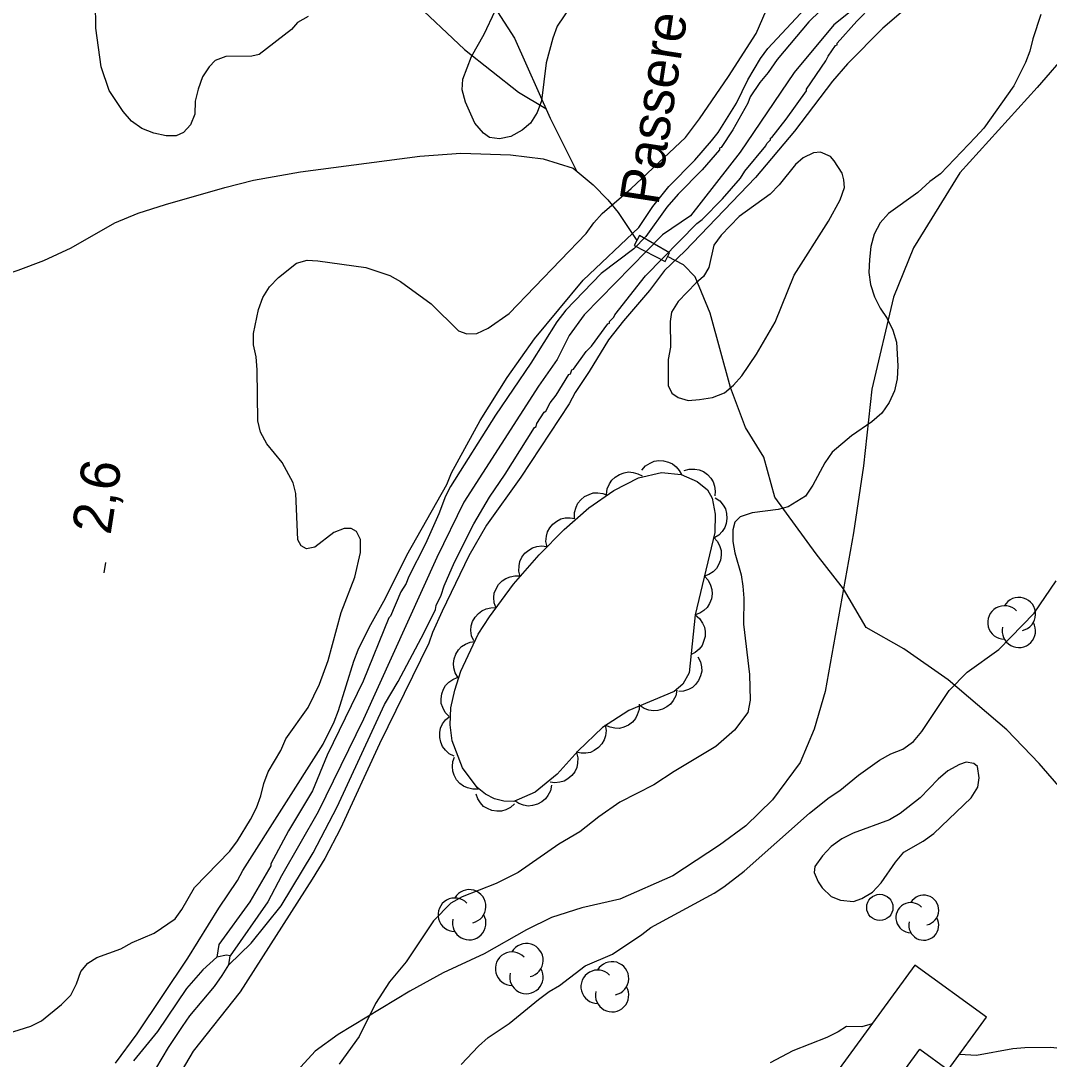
# Model space of a CAD drawing. Extents: x 282461 to 284471, y 5554090 to 5557646.
# Drawn here: x 283150.7 to 283229.1, y 5554690.7 to 5554769.8 of the extents above; entities that cross this region are included whole.
import ezdxf

# ---------------------------------------------------------------- set-up
doc = ezdxf.new("R2010")
doc.units = 0
for name, color, linetype in [('Niveau 2', 7, 'Continuous'), ('Niveau 22', 7, 'Continuous'), ('Niveau 26', 7, 'Continuous'), ('Niveau 3', 7, 'Continuous'), ('Niveau 31', 7, 'Continuous'), ('Niveau 36', 7, 'Continuous'), ('Niveau 4', 7, 'Continuous'), ('Niveau 44', 7, 'Continuous'), ('Niveau 7', 7, 'Continuous')]:
    doc.layers.add(name, color=color, linetype=linetype)

msp = doc.modelspace()

# ---------------------------------------------------------------- linework, layer by layer
at = {"layer": 'Niveau 2'}
for points in [[(283224.11, 5554775.88), (283216.37, 5554769.25), (283213.68, 5554766.53), (283212.54, 5554765.23), (283209.64, 5554761.41), (283206.67, 5554757.88), (283201.3, 5554752.27), (283199.75, 5554750.79), (283198.61, 5554749.27), (283196.62, 5554746.97), (283195.48, 5554745.5), (283194.01, 5554743.09), (283192.93, 5554741.51), (283192.48, 5554740.63), (283188.79, 5554735.05), (283186.18, 5554731.4), (283184.82, 5554729.06), (283182.8, 5554724.84), (283182.07, 5554723.21), (283181.79, 5554722.39), (283178.02, 5554714.72), (283175.05, 5554708.28), (283173.86, 5554706), (283172.9, 5554704.41), (283167.4, 5554695.85), (283163.82, 5554691.32), (283162.4, 5554688.91)], [(283172.58, 5554770.15), (283171.77, 5554769.68), (283171.32, 5554769.15), (283168.86, 5554767.25), (283168.28, 5554767.13), (283166.31, 5554767.09), (283165.5, 5554766.79), (283165.04, 5554766.32), (283164.53, 5554765.56), (283164.2, 5554764.62), (283163.98, 5554763.69), (283163.94, 5554762.71), (283163.61, 5554761.89), (283163.09, 5554761.3), (283162.52, 5554761.06), (283161.76, 5554761.05), (283160.83, 5554761.26), (283159.9, 5554761.6), (283159.13, 5554762.17), (283158.48, 5554762.91), (283157.41, 5554764.52), (283156.81, 5554766.3), (283156.41, 5554769.26), (283156.38, 5554771.23)], [(283157.91, 5554690.41), (283159.56, 5554692.64), (283163.41, 5554698.4), (283165.79, 5554702.21), (283167.21, 5554704.32), (283167.6, 5554705.09), (283173.72, 5554714.71), (283174.57, 5554716.41), (283174.9, 5554717.28), (283176.06, 5554721.02), (283176.4, 5554721.9), (283177.24, 5554723.59), (283178.48, 5554725.82), (283180.11, 5554729.1), (283183.16, 5554734.49), (283183.5, 5554735.37), (283185.7, 5554739.36), (283187.74, 5554742.64), (283189.84, 5554745.58), (283193.55, 5554750.06), (283197.78, 5554754.07), (283198.86, 5554755.66), (283200.06, 5554757.19), (283202.06, 5554759.2), (283203.31, 5554760.67), (283203.83, 5554761.32), (283205.24, 5554763.55), (283206.09, 5554765.31), (283207.05, 5554766.95), (283207.62, 5554767.71), (283210.82, 5554771.13)], [(283192.69, 5554771.07), (283191.56, 5554769.42), (283191.22, 5554768.49), (283190.73, 5554766.62), (283190.37, 5554763.71), (283190.04, 5554762.84), (283189.53, 5554762.02), (283188.9, 5554761.48), (283188.03, 5554761.01), (283187.17, 5554760.82), (283186.41, 5554760.92), (283185.94, 5554761.26), (283185.29, 5554762.01), (283184.57, 5554763.62), (283184.32, 5554764.55), (283184.36, 5554765.36), (283185.03, 5554767.11), (283185.99, 5554768.81), (283186.83, 5554770.57)], [(283194.98, 5554755.14), (283197.21, 5554757.03), (283201.33, 5554760.93), (283202.41, 5554762.34), (283204.62, 5554765.57), (283206.72, 5554768.85), (283207.5, 5554770.61)], [(283228.41, 5554770.31), (283227.81, 5554768.44), (283227.59, 5554767.5), (283227.25, 5554766.63), (283226.35, 5554764.87), (283224.08, 5554761.64), (283223.45, 5554760.94), (283220.77, 5554758.16), (283219.97, 5554757.57), (283219.05, 5554756.74), (283216.81, 5554755.14), (283216.18, 5554754.43), (283215.73, 5554753.55), (283215.46, 5554752.62), (283215.36, 5554751.63), (283215.31, 5554750.64), (283215.45, 5554749.72), (283215.75, 5554748.79), (283216.17, 5554747.93), (283216.71, 5554747.13), (283217.13, 5554746.26), (283217.43, 5554745.34), (283217.52, 5554743.54), (283217.48, 5554742.55), (283217.26, 5554741.62), (283216.87, 5554740.74), (283216.3, 5554739.92), (283215.55, 5554739.27), (283214, 5554738.2)], [(283212.68, 5554759.14), (283212.39, 5554759.48), (283211.63, 5554759.82), (283211.1, 5554759.75), (283210.3, 5554759.39), (283209.72, 5554758.86), (283208.47, 5554757.33), (283207.79, 5554756.62), (283205.43, 5554754.9), (283204.06, 5554753.48), (283203.49, 5554752.72), (283203.11, 5554751.03), (283202.72, 5554750.33), (283202.15, 5554749.85), (283200.78, 5554748.44), (283200.27, 5554747.62), (283200.16, 5554746.92), (283200.19, 5554744.95), (283200.03, 5554744.01), (283200.01, 5554742.04), (283200.31, 5554741.46), (283200.78, 5554741.12), (283201.54, 5554740.9), (283202.41, 5554740.97), (283203.39, 5554741.11), (283204.31, 5554741.47), (283205, 5554742.06), (283205.63, 5554742.77), (283206.76, 5554744.41), (283208.17, 5554746.87), (283209.63, 5554750.44), (283212.23, 5554754.54), (283213.14, 5554756.18), (283213.47, 5554757.12), (283213.4, 5554757.7), (283213.28, 5554758.22), (283212.68, 5554759.14)], [(283149.66, 5554692.66), (283151.45, 5554693.21), (283152.26, 5554693.63), (283153.8, 5554694.87), (283154.49, 5554695.58), (283154.94, 5554696.45), (283155.27, 5554697.39), (283155.79, 5554698.03), (283156.47, 5554698.45), (283158.32, 5554699.12), (283159.18, 5554699.6), (283160.86, 5554700.32), (283162.46, 5554701.39), (283162.97, 5554702.1), (283163.93, 5554703.79), (283166.62, 5554706.56), (283167.19, 5554707.33), (283168.2, 5554708.97), (283168.65, 5554709.85), (283168.99, 5554710.78), (283169.2, 5554711.71), (283169.54, 5554712.59), (283170.5, 5554714.23), (283170.89, 5554715.11), (283172.59, 5554717.51), (283173.44, 5554719.27), (283174.1, 5554721.08), (283175.09, 5554724.75), (283176.15, 5554727.44), (283176.58, 5554729.3), (283176.57, 5554730.29), (283176.27, 5554730.92), (283175.86, 5554731.15), (283175.34, 5554731.14), (283174.53, 5554730.84), (283173.09, 5554729.71), (283172.46, 5554729.58), (283172.05, 5554729.81), (283171.81, 5554730.27), (283171.64, 5554733.81), (283171.45, 5554734.62), (283170.61, 5554736.17), (283169.43, 5554737.6), (283168.95, 5554738.47), (283168.76, 5554739.33), (283168.7, 5554743.22), (283168.62, 5554744.21), (283168.43, 5554745.13), (283168.42, 5554746), (283168.8, 5554747.81), (283169.13, 5554748.74), (283169.64, 5554749.56), (283170.33, 5554750.27), (283171.7, 5554751.34), (283172.51, 5554751.58), (283173.32, 5554751.54), (283176.99, 5554751.02), (283178.8, 5554750.41), (283179.62, 5554749.96), (283181.97, 5554748.25), (283184.03, 5554746.2), (283184.68, 5554745.97), (283185.43, 5554745.99), (283186.29, 5554746.41), (283187.9, 5554747.53), (283193.78, 5554753.61), (283194.35, 5554754.43), (283194.98, 5554755.14)], [(283214, 5554738.2), (283212.51, 5554736.96), (283211.95, 5554736.13), (283211.05, 5554734.44), (283210.48, 5554733.61), (283209.16, 5554732.78), (283208.4, 5554732.59), (283206.43, 5554732.33), (283205.51, 5554732.03), (283205.11, 5554731.61), (283204.95, 5554731.03), (283204.96, 5554730.16), (283205.09, 5554729.29), (283205.58, 5554727.62), (283205.71, 5554726.75), (283205.78, 5554725.82), (283205.76, 5554723.85), (283206.22, 5554720.02), (283206.26, 5554718.05), (283206.1, 5554717.12), (283205.07, 5554715.77), (283203.64, 5554714.52), (283200.48, 5554712.62), (283198.93, 5554711.6), (283196.34, 5554710.29), (283194.73, 5554709.16), (283193.3, 5554708.03), (283191.69, 5554707.08), (283188.59, 5554704.94), (283186.92, 5554704.1), (283184.32, 5554703.07), (283183.46, 5554702.59), (283182.14, 5554701.24), (283180.05, 5554698.13), (283178.79, 5554696.6), (283177.72, 5554694.96), (283176.48, 5554692.44), (283174.95, 5554690.33)], [(283184.25, 5554690.3), (283185.56, 5554691.71), (283186.3, 5554692.36), (283187.91, 5554693.43), (283190.14, 5554695.26), (283190.94, 5554695.86), (283191.75, 5554696.33), (283193.7, 5554697.81), (283195.77, 5554698.72), (283198.01, 5554700.2), (283198.7, 5554700.74), (283203.53, 5554703.36), (283204.27, 5554703.84), (283205.82, 5554705.02), (283210.8, 5554709.45), (283212.29, 5554710.64), (283213.09, 5554711.17), (283214.52, 5554712.35), (283216.13, 5554713.48), (283216.99, 5554713.96), (283217.91, 5554714.32), (283218.72, 5554714.92), (283219.34, 5554715.68), (283221.44, 5554718.79), (283222.81, 5554720.2), (283225.22, 5554721.92), (283227.9, 5554724.69), (283229.6, 5554727.15)], [(283211.45, 5554704.23), (283211.75, 5554703.77), (283212.45, 5554703.09), (283213.15, 5554702.81), (283214.14, 5554702.71), (283214.78, 5554702.95), (283215.58, 5554703.43), (283216.26, 5554704.13), (283217.34, 5554705.71), (283217.97, 5554706.48), (283219.46, 5554707.31), (283220.26, 5554707.91), (283223.12, 5554710.62), (283223.62, 5554711.44), (283223.73, 5554712.13), (283223.6, 5554713), (283223.31, 5554713.23), (283222.73, 5554713.33), (283222.21, 5554713.15), (283221.34, 5554712.67), (283220.6, 5554712.03), (283219.23, 5554710.61), (283217.69, 5554709.43), (283216.88, 5554708.95), (283214.12, 5554707.92), (283213.25, 5554707.5), (283212.45, 5554706.91), (283211.77, 5554706.21), (283211.2, 5554705.39), (283211.15, 5554704.92), (283211.45, 5554704.23)], [(283215.56, 5554693.4), (283214.77, 5554693.16), (283213.61, 5554693.2), (283212.98, 5554692.78), (283212.11, 5554692.36), (283209.52, 5554691.34), (283207.79, 5554690.44)], [(283243.83, 5554692.72), (283243.61, 5554693.09), (283243.02, 5554693.55), (283242.32, 5554693.77), (283241.34, 5554693.64), (283239.55, 5554693.09), (283235.72, 5554692.62), (283234.86, 5554692.38), (283233.93, 5554692.25), (283231.45, 5554691.34), (283229.18, 5554691.59), (283227.21, 5554691.56), (283226.28, 5554691.49), (283223.51, 5554690.98), (283222.21, 5554691.07)]]:
    msp.add_lwpolyline(points, dxfattribs=at)
at = {"layer": 'Niveau 22'}
for points in [[(283179.89, 5554785.04), (283181.29, 5554780.85), (283182.12, 5554778.9), (283183.68, 5554775.68), (283184.87, 5554773.44), (283187.01, 5554770.51), (283188.32, 5554768.5), (283191.03, 5554762.39), (283193.07, 5554758.34)], [(283144.4, 5554779.69), (283145.96, 5554779.36), (283149.86, 5554778.84), (283154.29, 5554777.93), (283156.21, 5554777.72), (283157.78, 5554777.92), (283159.7, 5554777.83), (283161.67, 5554777.92), (283163.35, 5554777.89), (283164.93, 5554777.57), (283166.1, 5554777.06), (283166.92, 5554776.5), (283168.08, 5554776.05), (283170.53, 5554775.57), (283172.1, 5554775.36), (283173.67, 5554774.98), (283176, 5554774.21), (283178.16, 5554773.14), (283179.03, 5554772.58), (283180.5, 5554771.39), (283184.5, 5554767.62), (283188.62, 5554764.38), (283190.69, 5554763.13)], [(283230.61, 5554767.59), (283228.14, 5554764.73), (283222.24, 5554758.24), (283218.71, 5554752.53), (283217.19, 5554748.75), (283215.53, 5554741.75), (283214.91, 5554735.92), (283214.15, 5554730.81), (283211.98, 5554718.71), (283211.14, 5554715.86), (283210.07, 5554713.3), (283207.96, 5554710.47), (283205.95, 5554708.49), (283203.94, 5554707.02), (283200.37, 5554704.68), (283196.33, 5554702.91), (283193.44, 5554702.24), (283191.12, 5554701.5), (283189.22, 5554700.56), (283185.99, 5554698.73), (283182.87, 5554697.29), (283180.34, 5554695.88), (283174.86, 5554692.58), (283173.13, 5554691.33), (283166.57, 5554684.15)], [(283129.54, 5554744.82), (283131.68, 5554745.83), (283133.64, 5554746.62), (283141.55, 5554748.83), (283146.11, 5554749.49), (283147.73, 5554749.92), (283150.49, 5554750.83), (283152.45, 5554751.56), (283154.53, 5554752.52), (283157.86, 5554754.43), (283159.64, 5554755.15), (283161.72, 5554755.83), (283166.23, 5554757.12), (283168.42, 5554757.67), (283172.01, 5554758.31), (283181.09, 5554759.5), (283184.22, 5554759.73), (283188, 5554759.61), (283190.5, 5554759.3), (283192.78, 5554758.59), (283194.3, 5554757.33), (283195.43, 5554756.19), (283196.2, 5554755.21), (283197.64, 5554753.07)], [(283250.95, 5554693.69), (283248.15, 5554695.09), (283244.75, 5554697.58), (283235.92, 5554705.22), (283231.62, 5554709.39), (283228.3, 5554713.23), (283225.83, 5554715.8), (283221.37, 5554719.6), (283217.97, 5554721.97), (283215.11, 5554723.6), (283213.39, 5554726.53), (283211.3, 5554729.22), (283208.16, 5554733.52), (283207.3, 5554736.58), (283205.92, 5554738.82), (283204.77, 5554741.88), (283203.23, 5554747.55), (283202.08, 5554750.31), (283201.2, 5554751.23), (283199.97, 5554751.85)]]:
    msp.add_lwpolyline(points, dxfattribs=at)
at = {"layer": 'Niveau 26'}
msp.add_lwpolyline([(283197.84, 5554753.45), (283197.44, 5554752.69), (283199.79, 5554751.48), (283200.12, 5554752.15), (283197.84, 5554753.45)], dxfattribs=at)
at = {"layer": 'Niveau 3'}
msp.add_line((283157.04, 5554727.75), (283157.16, 5554728.54), dxfattribs=at)
at = {"layer": 'Niveau 31'}
msp.add_lwpolyline([(283213.13, 5554683.14), (283219.21, 5554691.46), (283221.35, 5554689.9), (283224.27, 5554693.9), (283218.82, 5554697.87), (283209.82, 5554685.56), (283213.13, 5554683.14)], dxfattribs=at)
at = {"layer": 'Niveau 36'}
msp.add_circle((283216.149, 5554702.268), 1, dxfattribs=at)
at = {"layer": 'Niveau 4'}
for points in [[(283216.27, 5554772.44), (283212.65, 5554769.51), (283209.61, 5554765.88), (283205.5, 5554759.81), (283201.73, 5554754.96), (283199.59, 5554753.5), (283193.62, 5554747.41), (283192.48, 5554745.83), (283191.57, 5554744.02), (283190.15, 5554741.98), (283184.44, 5554733.14), (283182.4, 5554728.94), (283176.8, 5554716.6), (283173.34, 5554709.55), (283170.55, 5554704.68), (283169.52, 5554702.7), (283166.65, 5554698.59)], [(283160.97, 5554689.96), (283161.93, 5554691.6), (283163.01, 5554693.19), (283163.58, 5554694.01), (283165.46, 5554696.25), (283166.03, 5554697.07), (283166.54, 5554697.89), (283166.65, 5554698.59), (283166.35, 5554698.64), (283165.63, 5554698.49), (283164.57, 5554697.51), (283163.31, 5554696.1), (283161.1, 5554692.81), (283159.28, 5554690.57)]]:
    msp.add_lwpolyline(points, dxfattribs=at)
at = {"layer": 'Niveau 44'}
for points in [[(283198.02, 5554735.58), (283198.3, 5554735.9), (283198.64, 5554736.12), (283198.95, 5554736.26), (283199.3, 5554736.31), (283199.67, 5554736.3), (283200.04, 5554736.2), (283200.35, 5554736.07), (283200.62, 5554735.84), (283200.87, 5554735.56), (283201.04, 5554735.24)], [(283202.09, 5554724.55), (283201.62, 5554720.14), (283201.15, 5554719.28), (283200.48, 5554718.73), (283197.03, 5554717.26), (283195.02, 5554715.98), (283193.15, 5554714.21), (283191.56, 5554712.41), (283189.88, 5554711.04), (283188.25, 5554710.34), (283187.49, 5554710.36), (283186.78, 5554710.54), (283186.09, 5554710.89), (283185.46, 5554711.41), (283184.34, 5554712.91), (283183.56, 5554714.97), (283183.4, 5554716.17), (283183.46, 5554717.47), (283183.75, 5554718.83), (283184.23, 5554720.26), (283185.53, 5554723.08), (283186.4, 5554724.4), (283188.24, 5554726.89), (283190.2, 5554729.13), (283192.09, 5554731.06), (283193.98, 5554732.7), (283195.89, 5554734.03), (283197.76, 5554735), (283199.51, 5554735.41), (283201.02, 5554735.24), (283202.23, 5554734.73), (283203.01, 5554734.09), (283203.37, 5554733.45), (283203.59, 5554732.23), (283203.58, 5554730.83), (283202.09, 5554724.55)], [(283195.33, 5554733.74), (283195.38, 5554734.16), (283195.55, 5554734.54), (283195.72, 5554734.82), (283195.98, 5554735.06), (283196.3, 5554735.26), (283196.67, 5554735.38), (283196.99, 5554735.45), (283197.35, 5554735.41), (283197.71, 5554735.31), (283198.03, 5554735.14)], [(283201.23, 5554735.55), (283201.63, 5554735.67), (283202.04, 5554735.67), (283202.37, 5554735.62), (283202.7, 5554735.48), (283203.01, 5554735.26), (283203.26, 5554734.97), (283203.45, 5554734.7), (283203.56, 5554734.36), (283203.61, 5554733.99), (283203.57, 5554733.63)], [(283192.89, 5554731.94), (283192.88, 5554732.36), (283193, 5554732.76), (283193.13, 5554733.06), (283193.36, 5554733.33), (283193.65, 5554733.57), (283194, 5554733.74), (283194.31, 5554733.85), (283194.67, 5554733.85), (283195.04, 5554733.8), (283195.38, 5554733.67)], [(283203.6, 5554733.48), (283203.95, 5554733.24), (283204.2, 5554732.92), (283204.38, 5554732.63), (283204.46, 5554732.28), (283204.49, 5554731.91), (283204.43, 5554731.53), (283204.34, 5554731.21), (283204.14, 5554730.92), (283203.88, 5554730.64), (283203.58, 5554730.44)], [(283190.79, 5554729.73), (283190.7, 5554730.14), (283190.74, 5554730.55), (283190.82, 5554730.88), (283190.99, 5554731.19), (283191.23, 5554731.48), (283191.54, 5554731.7), (283191.83, 5554731.87), (283192.18, 5554731.94), (283192.55, 5554731.96), (283192.91, 5554731.9)], [(283188.75, 5554727.48), (283188.65, 5554727.89), (283188.66, 5554728.3), (283188.72, 5554728.63), (283188.88, 5554728.95), (283189.1, 5554729.25), (283189.4, 5554729.49), (283189.67, 5554729.67), (283190.02, 5554729.77), (283190.39, 5554729.81), (283190.75, 5554729.76)], [(283203.49, 5554730.45), (283203.78, 5554730.14), (283203.95, 5554729.77), (283204.06, 5554729.45), (283204.07, 5554729.1), (283204.01, 5554728.73), (283203.86, 5554728.37), (283203.7, 5554728.08), (283203.44, 5554727.84), (283203.13, 5554727.63), (283202.79, 5554727.5)], [(283186.9, 5554725.08), (283186.76, 5554725.48), (283186.74, 5554725.89), (283186.77, 5554726.22), (283186.9, 5554726.55), (283187.1, 5554726.87), (283187.38, 5554727.14), (283187.64, 5554727.34), (283187.97, 5554727.46), (283188.34, 5554727.53), (283188.7, 5554727.52)], [(283202.79, 5554727.5), (283203.08, 5554727.19), (283203.25, 5554726.82), (283203.36, 5554726.5), (283203.37, 5554726.15), (283203.31, 5554725.78), (283203.16, 5554725.42), (283203, 5554725.13), (283202.74, 5554724.89), (283202.43, 5554724.68), (283202.09, 5554724.55)], [(283185.2, 5554722.57), (283185.03, 5554722.96), (283184.99, 5554723.37), (283185.01, 5554723.71), (283185.12, 5554724.04), (283185.3, 5554724.37), (283185.56, 5554724.65), (283185.81, 5554724.87), (283186.14, 5554725.01), (283186.5, 5554725.1), (283186.86, 5554725.11)], [(283202.09, 5554724.55), (283202.41, 5554724.28), (283202.64, 5554723.93), (283202.78, 5554723.63), (283202.83, 5554723.28), (283202.83, 5554722.91), (283202.72, 5554722.53), (283202.6, 5554722.23), (283202.37, 5554721.95), (283202.09, 5554721.7), (283201.77, 5554721.53)], [(283184.01, 5554719.77), (283183.79, 5554720.13), (283183.69, 5554720.53), (283183.65, 5554720.86), (283183.71, 5554721.22), (283183.83, 5554721.57), (283184.05, 5554721.89), (283184.27, 5554722.14), (283184.57, 5554722.33), (283184.92, 5554722.47), (283185.28, 5554722.53)], [(283202.29, 5554721.37), (283202.49, 5554720.99), (283202.56, 5554720.59), (283202.58, 5554720.26), (283202.49, 5554719.91), (283202.34, 5554719.57), (283202.1, 5554719.26), (283201.87, 5554719.03), (283201.56, 5554718.86), (283201.2, 5554718.74), (283200.84, 5554718.71)], [(283183.32, 5554716.81), (283183.03, 5554717.12), (283182.84, 5554717.49), (283182.73, 5554717.8), (283182.71, 5554718.16), (283182.76, 5554718.53), (283182.9, 5554718.89), (283183.06, 5554719.18), (283183.31, 5554719.43), (283183.62, 5554719.64), (283183.95, 5554719.78)], [(283200.68, 5554718.81), (283200.6, 5554718.4), (283200.41, 5554718.04), (283200.21, 5554717.76), (283199.93, 5554717.55), (283199.6, 5554717.37), (283199.22, 5554717.28), (283198.9, 5554717.24), (283198.55, 5554717.3), (283198.19, 5554717.43), (283197.89, 5554717.63)], [(283197.82, 5554717.76), (283197.8, 5554717.34), (283197.67, 5554716.95), (283197.53, 5554716.65), (283197.29, 5554716.39), (283196.99, 5554716.16), (283196.63, 5554716.01), (283196.32, 5554715.91), (283195.96, 5554715.92), (283195.59, 5554715.99), (283195.26, 5554716.13)], [(283183.72, 5554713.79), (283183.34, 5554713.98), (283183.04, 5554714.26), (283182.83, 5554714.52), (283182.69, 5554714.85), (283182.61, 5554715.21), (283182.63, 5554715.6), (283182.67, 5554715.93), (283182.83, 5554716.25), (283183.04, 5554716.55), (283183.32, 5554716.8)], [(283195.22, 5554716.17), (283195.29, 5554715.76), (283195.24, 5554715.35), (283195.15, 5554715.03), (283194.96, 5554714.72), (283194.72, 5554714.45), (283194.39, 5554714.23), (283194.1, 5554714.08), (283193.75, 5554714.01), (283193.38, 5554714.01), (283193.02, 5554714.09)], [(283193.03, 5554714.08), (283193.14, 5554713.67), (283193.12, 5554713.26), (283193.06, 5554712.93), (283192.9, 5554712.61), (283192.68, 5554712.31), (283192.38, 5554712.07), (283192.1, 5554711.89), (283191.76, 5554711.8), (283191.39, 5554711.76), (283191.02, 5554711.8)], [(283185.55, 5554711.29), (283185.13, 5554711.27), (283184.73, 5554711.37), (283184.42, 5554711.5), (283184.14, 5554711.72), (283183.89, 5554712), (283183.72, 5554712.34), (283183.6, 5554712.65), (283183.58, 5554713), (283183.62, 5554713.38), (283183.74, 5554713.72)], [(283191.13, 5554711.58), (283191.05, 5554711.16), (283190.86, 5554710.8), (283190.66, 5554710.53), (283190.39, 5554710.31), (283190.06, 5554710.13), (283189.68, 5554710.04), (283189.35, 5554709.99), (283189, 5554710.06), (283188.65, 5554710.18), (283188.34, 5554710.38)], [(283188.32, 5554710.15), (283188.01, 5554709.87), (283187.64, 5554709.7), (283187.32, 5554709.6), (283186.96, 5554709.59), (283186.59, 5554709.65), (283186.24, 5554709.81), (283185.95, 5554709.97), (283185.71, 5554710.24), (283185.51, 5554710.55), (283185.38, 5554710.89)]]:
    msp.add_lwpolyline(points, dxfattribs=at)
for centre, radius, start, end in [((283226.744, 5554724.616), 1.275, 282.26917, 149.72625), ((283225.647, 5554723.978), 1.275, 44.11537, 269.80396), ((283226.744, 5554723.341), 1.275, 166.93686, 29.62122), ((283183.763, 5554701.712), 1.275, 44.11537, 269.80396), ((283184.86, 5554702.349), 1.275, 282.26917, 149.72625), ((283219.499, 5554702.061), 1.144, 282.26917, 149.72625), ((283218.515, 5554701.489), 1.144, 44.11537, 269.80396), ((283184.86, 5554701.074), 1.275, 166.93686, 29.62122), ((283219.499, 5554700.916), 1.144, 166.93686, 29.62122), ((283189.22, 5554698.241), 1.275, 282.26917, 149.72625), ((283188.123, 5554697.603), 1.275, 44.11537, 269.80396), ((283195.743, 5554696.861), 1.275, 282.26917, 149.72625), ((283189.22, 5554696.966), 1.275, 166.93686, 29.62122), ((283194.646, 5554696.224), 1.275, 44.11537, 269.80396), ((283195.743, 5554695.586), 1.275, 166.93686, 29.62122)]:
    msp.add_arc(centre, radius, start, end, dxfattribs=at)
at = {"layer": 'Niveau 7'}
for points in [[(283166.54, 5554697.89), (283168.23, 5554699.55), (283170.52, 5554702.39), (283172.97, 5554706.44), (283174.79, 5554709.94), (283178.41, 5554717.74), (283179.44, 5554719.49), (283181.43, 5554723.22), (283182.28, 5554724.97), (283182.33, 5554725.26), (283182.73, 5554726.07), (283182.95, 5554726.77), (283183.74, 5554728.58), (283185.22, 5554731.49), (283186.41, 5554733.53), (283187.61, 5554735.28), (283189.83, 5554738.84), (283189.95, 5554738.9), (283190.01, 5554739.13), (283190.58, 5554740.01), (283190.69, 5554740.07), (283191.03, 5554740.71), (283191.49, 5554741.29), (283192.46, 5554742.87), (283192.57, 5554742.93), (283192.69, 5554743.22), (283192.8, 5554743.28), (283193.77, 5554744.62), (283194.18, 5554745.03), (283195.43, 5554746.72), (283195.55, 5554746.78), (283195.55, 5554746.9), (283195.89, 5554747.25), (283195.95, 5554747.42), (283198.29, 5554750.4), (283202.2, 5554754.38), (283202.6, 5554754.67), (283204.15, 5554756.25), (283205.53, 5554757.83), (283205.87, 5554758.36), (283207.47, 5554760.29), (283207.53, 5554760.46), (283207.81, 5554760.75), (283207.81, 5554760.87), (283207.93, 5554760.93), (283209.02, 5554762.33), (283210.56, 5554764.49), (283210.56, 5554764.61), (283212.04, 5554766.77), (283212.21, 5554767.12), (283212.78, 5554767.93), (283212.9, 5554767.99), (283212.9, 5554768.11), (283214.39, 5554769.8), (283215.54, 5554770.97)], [(283212.45, 5554771.38), (283210.73, 5554769.74), (283208.32, 5554766.88), (283207.64, 5554765.88), (283207.01, 5554765.12), (283206.27, 5554764.02), (283206.1, 5554763.55), (283204.96, 5554761.51), (283204.05, 5554760.17), (283203.93, 5554760.11), (283203.93, 5554759.99)], [(283203.93, 5554759.99), (283202.61, 5554758.47), (283200.78, 5554756.6), (283199.92, 5554755.61), (283198.32, 5554753.39), (283197.4, 5554752.45), (283194.92, 5554750.57), (283192.23, 5554747.77), (283191.54, 5554746.89), (283189.55, 5554743.74), (283186.86, 5554739.77), (283183.44, 5554734.35), (283183.05, 5554733.59), (283182.54, 5554732.25), (283181.52, 5554729.98), (283180.22, 5554727.42), (283180.05, 5554726.95), (283179.65, 5554726.31), (283178.86, 5554724.45), (283178.74, 5554724.33), (283176.77, 5554719.5), (283174.04, 5554713.88), (283172.92, 5554711.14), (283171.09, 5554708.11), (283169.73, 5554705.6), (283169.73, 5554705.43), (283168.14, 5554702.69), (283165.79, 5554699.45), (283165.63, 5554698.49)]]:
    msp.add_lwpolyline(points, dxfattribs=at)

# ---------------------------------------------------------------- texts
at = {"layer": 'Niveau 26'}
msp.add_text('Passerelle', height=3, rotation=81.30751, dxfattribs=at).set_placement((283199.27, 5554755.69))
at = {"layer": 'Niveau 3'}
msp.add_text('2,6  ', height=3, rotation=81.09575, dxfattribs=at).set_placement((283157.52, 5554730.59))

doc.saveas('drawing.dxf')
